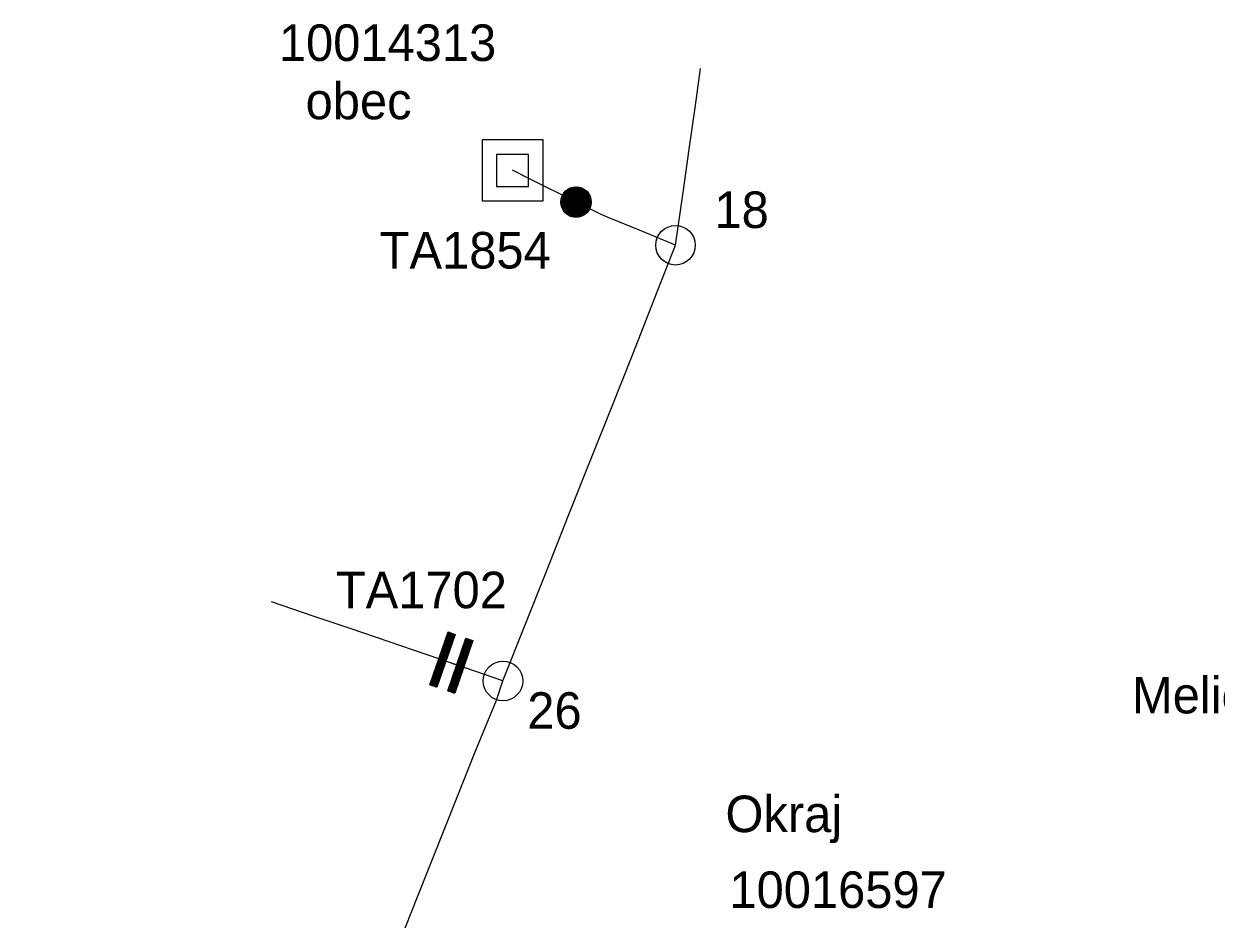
# Model space of a CAD drawing. Extents: x -749194 to -734612, y -1146817 to -1138558.
# Drawn here: x -744445 to -742487, y -1140028 to -1138558 of the extents above; entities that cross this region are included whole.
import ezdxf

# ---------------------------------------------------------------- set-up
doc = ezdxf.new("R2010")
doc.units = 0
for name, color, linetype in [('Default', 7, 'Continuous'), ('Vrstva 1', 7, 'Continuous'), ('Vrstva 18', 7, 'Continuous'), ('Vrstva 2', 7, 'Continuous'), ('Vrstva 3', 7, 'Continuous'), ('Vrstva 5', 7, 'Continuous')]:
    doc.layers.add(name, color=color, linetype=linetype)

# ---------------------------------------------------------------- blocks, each defined once
blk = doc.blocks.new('PS440')
at = {"layer": 'Default'}
for p, q in [((-25, 0.1), (-0.1, 25)), ((-24.9, -1.2), (1.2, 24.9)), ((-24.9, 1.6), (-1.6, 24.9)), ((-24.8, -2.6), (2.6, 24.8)), ((-24.8, 3.2), (-3.2, 24.8)), ((-24.7, -3.8), (3.8, 24.7)), ((-24.5, -5), (5, 24.5)), ((-24.5, 4.9), (-4.9, 24.5)), ((-24.2, -6.2), (6.2, 24.2)), ((-24.1, 6.7), (-6.7, 24.1)), ((-23.9, -7.3), (7.3, 23.9)), ((-23.6, -8.3), (8.3, 23.6)), ((-23.4, 8.8), (-8.8, 23.4)), ((-23.2, -9.4), (9.4, 23.2)), ((-22.7, -10.3), (10.3, 22.7)), ((-22.3, -11.3), (11.3, 22.3)), ((-22.3, 11.3), (-11.3, 22.3)), ((-21.8, -12.2), (12.2, 21.8)), ((-21.3, -13.1), (13.1, 21.3)), ((-20.7, -14), (14, 20.7)), ((-20.1, -14.8), (14.8, 20.1)), ((-19.9, 15.2), (-15.2, 19.9)), ((-19.5, -15.6), (15.6, 19.5)), ((-18.9, -16.4), (16.4, 18.9)), ((-18.2, -17.1), (17.1, 18.2)), ((-17.5, -17.8), (17.8, 17.5)), ((-16.8, -18.5), (18.5, 16.8)), ((-16, -19.2), (19.2, 16)), ((-15.2, -19.8), (19.8, 15.2)), ((-14.4, -20.4), (20.4, 14.4)), ((-13.6, -21), (21, 13.6)), ((-12.7, -21.5), (21.5, 12.7)), ((-11.8, -22), (22, 11.8)), ((-10.8, -22.5), (22.5, 10.8)), ((-9.9, -22.9), (22.9, 9.9)), ((-8.9, -23.4), (23.4, 8.9)), ((-7.8, -23.7), (23.7, 7.8)), ((-6.7, -24.1), (24.1, 6.7)), ((-5.6, -24.3), (24.3, 5.6)), ((-4.4, -24.6), (24.6, 4.4)), ((-3.2, -24.8), (24.8, 3.2)), ((-1.9, -24.9), (24.9, 1.9)), ((-0.6, -25), (25, 0.6)), ((0.8, -25), (25, -0.8)), ((2.3, -24.9), (24.9, -2.3)), ((4, -24.7), (24.7, -4)), ((5.7, -24.3), (24.3, -5.7)), ((7.7, -23.8), (23.8, -7.7)), ((10, -22.9), (22.9, -10)), ((12.9, -21.4), (21.4, -12.9))]:
    blk.add_line(p, q, dxfattribs=at)
blk.add_circle((0, 0), 25, dxfattribs=at)
blk = doc.blocks.new('PS820')
at = {"layer": 'Vrstva 2'}
blk.add_circle((0, 0), 32.5, dxfattribs=at)
blk = doc.blocks.new('PS450')
at = {"layer": 'Default'}
for p, q in [((-22.1, 35.1), (-10.4, 46.8)), ((-22.1, 36.5), (-11.8, 46.8)), ((-22.1, 38), (-13.3, 46.8)), ((-22.1, 39.4), (-14.7, 46.8)), ((-22.1, 40.8), (-16.1, 46.8)), ((-22.1, 42.2), (-17.5, 46.8)), ((-22.1, 43.6), (-18.9, 46.8)), ((-22.1, 45), (-20.3, 46.8)), ((-22.1, 46.4), (-21.7, 46.8)), ((-22.1, 33.7), (-9.9, 45.9)), ((-22.1, 32.3), (-9.9, 44.5)), ((-22.1, 30.9), (-9.9, 43.1)), ((-22.1, 29.5), (-9.9, 41.7)), ((-22.1, 28.1), (-9.9, 40.3)), ((8.9, 35.2), (20.5, 46.8)), ((8.9, 36.7), (19.1, 46.8)), ((8.9, 38.1), (17.6, 46.8)), ((8.9, 39.5), (16.2, 46.8)), ((8.9, 40.9), (14.8, 46.8)), ((8.9, 42.3), (13.4, 46.8)), ((8.9, 43.7), (12, 46.8)), ((8.9, 45.1), (10.6, 46.8)), ((8.9, 46.6), (9.2, 46.8)), ((8.9, 33.8), (21.1, 46.1)), ((8.9, 32.4), (21.1, 44.6)), ((8.9, 31), (21.1, 43.2)), ((8.9, 29.6), (21.1, 41.8)), ((8.9, 28.2), (21.1, 40.4)), ((-22.1, 26.6), (-9.9, 38.9)), ((-22.1, 25.2), (-9.9, 37.5)), ((-22.1, 23.8), (-9.9, 36)), ((-22.1, 22.4), (-9.9, 34.6)), ((-22.1, 21), (-9.9, 33.2)), ((-22.1, 19.6), (-9.9, 31.8)), ((-22.1, 18.2), (-9.9, 30.4)), ((-22.1, 16.7), (-9.9, 29)), ((-22.1, 15.3), (-9.9, 27.6)), ((-22.1, 13.9), (-9.9, 26.1)), ((-22.1, 12.5), (-9.9, 24.7)), ((-22.1, 11.1), (-9.9, 23.3)), ((-22.1, 9.7), (-9.9, 21.9)), ((-22.1, 8.3), (-9.9, 20.5)), ((8.9, 26.8), (21.1, 39)), ((8.9, 25.3), (21.1, 37.6)), ((8.9, 23.9), (21.1, 36.2)), ((8.9, 22.5), (21.1, 34.7)), ((8.9, 21.1), (21.1, 33.3)), ((8.9, 19.7), (21.1, 31.9)), ((8.9, 18.3), (21.1, 30.5)), ((8.9, 16.9), (21.1, 29.1)), ((8.9, 15.5), (21.1, 27.7)), ((8.9, 14), (21.1, 26.3)), ((8.9, 12.6), (21.1, 24.9)), ((8.9, 11.2), (21.1, 23.4)), ((8.9, 9.8), (21.1, 22)), ((8.9, 8.4), (21.1, 20.6)), ((-22.1, 6.8), (-9.9, 19.1)), ((-22.1, 5.4), (-9.9, 17.7)), ((-22.1, 4), (-9.9, 16.2)), ((-22.1, 2.6), (-9.9, 14.8)), ((-22.1, 1.2), (-9.9, 13.4)), ((-22.1, -0.2), (-9.9, 12)), ((-22.1, -1.6), (-9.9, 10.6)), ((-22.1, -3.1), (-9.9, 9.2)), ((-22.1, -4.5), (-9.9, 7.8)), ((-22.1, -5.9), (-9.9, 6.3)), ((-22.1, -7.3), (-9.9, 4.9)), ((-22.1, -8.7), (-9.9, 3.5)), ((-22.1, -10.1), (-9.9, 2.1)), ((-22.1, -11.5), (-9.9, 0.7)), ((8.9, 7), (21.1, 19.2)), ((8.9, 5.6), (21.1, 17.8)), ((8.9, 4.1), (21.1, 16.4)), ((8.9, 2.7), (21.1, 15)), ((8.9, 1.3), (21.1, 13.5)), ((8.9, -0.1), (21.1, 12.1)), ((8.9, -1.5), (21.1, 10.7)), ((8.9, -2.9), (21.1, 9.3)), ((8.9, -4.3), (21.1, 7.9)), ((8.9, -5.8), (21.1, 6.5)), ((8.9, -7.2), (21.1, 5.1)), ((8.9, -8.6), (21.1, 3.6)), ((8.9, -10), (21.1, 2.2)), ((8.9, -11.4), (21.1, 0.8)), ((-22.1, -13), (-9.9, -0.7)), ((-22.1, -14.4), (-9.9, -2.1)), ((-22.1, -15.8), (-9.9, -3.6)), ((-22.1, -17.2), (-9.9, -5)), ((-22.1, -18.6), (-9.9, -6.4)), ((-22.1, -20), (-9.9, -7.8)), ((-22.1, -21.4), (-9.9, -9.2)), ((-22.1, -22.9), (-9.9, -10.6)), ((-22.1, -24.3), (-9.9, -12)), ((-22.1, -25.7), (-9.9, -13.5)), ((-22.1, -27.1), (-9.9, -14.9)), ((-22.1, -28.5), (-9.9, -16.3)), ((-22.1, -29.9), (-9.9, -17.7)), ((-22.1, -31.3), (-9.9, -19.1)), ((8.9, -12.8), (21.1, -0.6)), ((8.9, -14.2), (21.1, -2)), ((8.9, -15.7), (21.1, -3.4)), ((8.9, -17.1), (21.1, -4.8)), ((8.9, -18.5), (21.1, -6.3)), ((8.9, -19.9), (21.1, -7.7)), ((8.9, -21.3), (21.1, -9.1)), ((8.9, -22.7), (21.1, -10.5)), ((8.9, -24.1), (21.1, -11.9)), ((8.9, -25.6), (21.1, -13.3)), ((8.9, -27), (21.1, -14.7)), ((8.9, -28.4), (21.1, -16.2)), ((8.9, -29.8), (21.1, -17.6)), ((8.9, -31.2), (21.1, -19)), ((-22.1, -32.8), (-9.9, -20.5)), ((-22.1, -34.2), (-9.9, -21.9)), ((-22.1, -35.6), (-9.9, -23.4)), ((-22.1, -37), (-9.9, -24.8)), ((-22.1, -38.4), (-9.9, -26.2)), ((-22.1, -39.8), (-9.9, -27.6)), ((-22.1, -41.2), (-9.9, -29)), ((-22.1, -42.7), (-9.9, -30.4)), ((-22.1, -44.1), (-9.9, -31.8)), ((-21.5, -44.9), (-9.9, -33.3)), ((-20.1, -44.9), (-9.9, -34.7)), ((-18.7, -44.9), (-9.9, -36.1)), ((-17.3, -44.9), (-9.9, -37.5)), ((-15.8, -44.9), (-9.9, -38.9)), ((8.9, -32.6), (21.1, -20.4)), ((8.9, -34), (21.1, -21.8)), ((8.9, -35.5), (21.1, -23.2)), ((8.9, -36.9), (21.1, -24.6)), ((8.9, -38.3), (21.1, -26.1)), ((8.9, -39.7), (21.1, -27.5)), ((8.9, -41.1), (21.1, -28.9)), ((8.9, -42.5), (21.1, -30.3)), ((8.9, -43.9), (21.1, -31.7)), ((9.4, -44.9), (21.1, -33.1)), ((10.8, -44.9), (21.1, -34.5)), ((12.2, -44.9), (21.1, -36)), ((13.6, -44.9), (21.1, -37.4)), ((15, -44.9), (21.1, -38.8)), ((-14.4, -44.9), (-9.9, -40.3)), ((-13, -44.9), (-9.9, -41.7)), ((-11.6, -44.9), (-9.9, -43.2)), ((-10.2, -44.9), (-9.9, -44.6)), ((16.5, -44.9), (21.1, -40.2)), ((17.9, -44.9), (21.1, -41.6)), ((19.3, -44.9), (21.1, -43)), ((20.7, -44.9), (21.1, -44.4))]:
    blk.add_line(p, q, dxfattribs=at)
for points in [[(-9.9, 46.8), (-9.9, -44.9), (-22.1, -44.9), (-22.1, 46.8)], [(21.1, 46.8), (21.1, -44.9), (8.9, -44.9), (8.9, 46.8)]]:
    blk.add_lwpolyline(points, close=True, dxfattribs=at)
blk = doc.blocks.new('PS645')
at = {"layer": 'Vrstva 18'}
for points in [[(50, 49.7), (-50, 49.7)], [(-50, 49.7), (-50, -50.3)], [(50, -50.3), (50, 49.7)], [(26.4, 26), (-26.3, 26)], [(-26.3, 26), (-26.3, -26.7)], [(26.4, -26.7), (26.4, 26)], [(-26.3, -26.7), (26.4, -26.7)], [(-50, -50.3), (50, -50.3)]]:
    blk.add_lwpolyline(points, dxfattribs=at)

msp = doc.modelspace()

# ---------------------------------------------------------------- linework, layer by layer
at = {"layer": 'Vrstva 1'}
for points in [[(-743375.1, -1138921.6), (-743375.1, -1138921.6), (-743362.8, -1138835), (-743352.6, -1138763.8), (-743342.4, -1138692.2), (-743334.2, -1138631.3)], [(-743538.5, -1138850.6), (-743538.4, -1138850.5), (-743538.8, -1138850.3), (-743614.8, -1138812.4), (-743642.8, -1138798.4)], [(-743375.1, -1138921.6), (-743375.1, -1138921.6), (-743430.5, -1138898.7), (-743485.9, -1138875.8), (-743497.1, -1138871.1), (-743538.4, -1138850.5), (-743538.5, -1138850.6)], [(-743658.5, -1139637.1), (-743658.5, -1139637.1), (-743622, -1139544.8), (-743586.7, -1139455.7), (-743551.3, -1139366.7), (-743515.7, -1139277.4), (-743480.3, -1139188.4), (-743445.4, -1139100.3), (-743410.2, -1139010.8), (-743375.1, -1138921.6), (-743375.1, -1138921.6)], [(-743743.1, -1139608), (-743720.7, -1139615.7), (-743783.2, -1139594.2), (-743807, -1139586), (-743845.6, -1139572.9), (-743907.8, -1139551.7), (-743970.4, -1139530.4), (-744038.7, -1139507.2)], [(-743658.5, -1139637.1), (-743658.5, -1139637.1), (-743720.7, -1139615.7), (-743720.7, -1139615.7), (-743743.1, -1139608)], [(-744428.7, -1141564.5), (-744445.5, -1141607.1), (-744412.3, -1141524.8), (-744364.3, -1141408.1), (-744316.2, -1141289.2), (-744269.4, -1141171.4), (-744222.8, -1141053.9), (-744175.7, -1140935.2), (-744128.4, -1140816), (-744082, -1140699.4), (-744035, -1140581.8), (-743986.9, -1140464.2), (-743938.9, -1140347.2), (-743891.8, -1140228.5), (-743845.2, -1140109.4), (-743799, -1139991.5), (-743751.9, -1139873.3), (-743705.2, -1139756.1), (-743669.4, -1139668.7), (-743658.5, -1139637.1), (-743658.5, -1139637.1)]]:
    msp.add_lwpolyline(points, dxfattribs=at)

# ---------------------------------------------------------------- block references
at = {"layer": 'Vrstva 2'}
for name, p, rotation in [('PS440', (-743538.5, -1138850.6), -21.318066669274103), ('PS450', (-743743.1, -1139608), -18.989286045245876)]:
    msp.add_blockref(name, p, dxfattribs=dict(at, rotation=rotation))
at = {"layer": 'Vrstva 3'}
msp.add_blockref('PS645', (-743642.8, -1138798.4), dxfattribs=at)
at = {"layer": 'Vrstva 5'}
for p, rotation in [((-743375.1, -1138921.6), 81.86487779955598), ((-743658.5, -1139637.1), 68.38534994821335)]:
    msp.add_blockref('PS820', p, dxfattribs=dict(at, rotation=rotation))

# ---------------------------------------------------------------- texts
at = {"layer": 'Vrstva 2'}
for s, p in [('TA1854', (-743861.1, -1138959.8)), ('TA1702', (-743933.1, -1139517.6))]:
    msp.add_text(s, height=60, dxfattribs=at).set_placement(p)
at = {"layer": 'Vrstva 3'}
for s, p in [('10014313', (-744026.6, -1138619)), ('obec', (-743982.7, -1138714.7)), ('Meliorace  B 14', (-742625.4, -1139690.3)), ('Okraj', (-743293.1, -1139885.3)), ('10016597', (-743286.6, -1140009.8))]:
    msp.add_text(s, height=60, dxfattribs=at).set_placement(p)
at = {"layer": 'Vrstva 5'}
for s, p in [('18', (-743311.2, -1138893.3)), ('26', (-743618.6, -1139715.6))]:
    msp.add_text(s, height=60, dxfattribs=at).set_placement(p)

doc.saveas('drawing.dxf')
